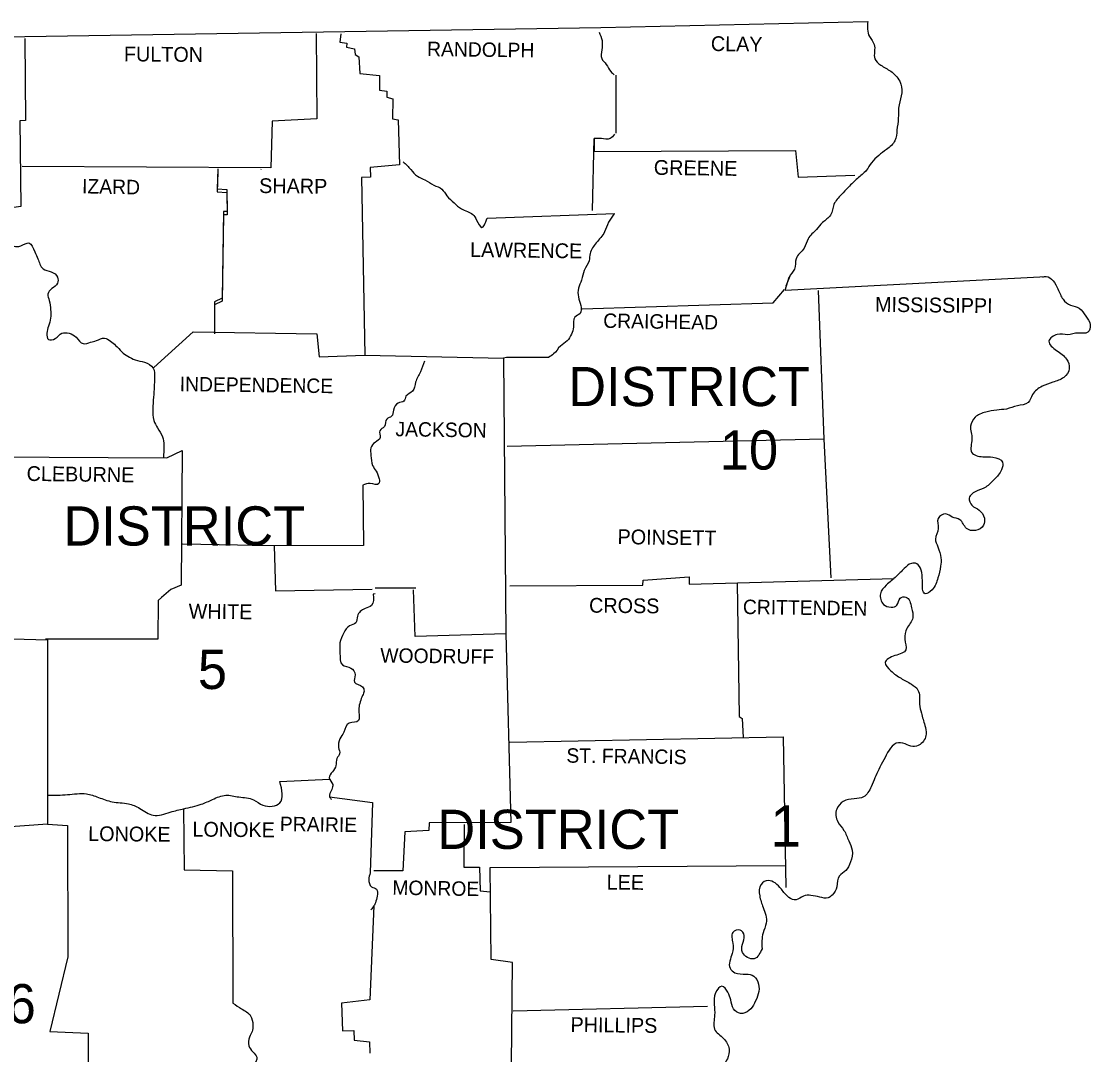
# Model space of a CAD drawing. Extents: x -33639 to 34530, y -17264 to 5867.
# Drawn here: x 2998 to 4708, y 4213 to 5867 of the extents above; entities that cross this region are included whole.
import ezdxf

# ---------------------------------------------------------------- set-up
doc = ezdxf.new("R2010")
doc.units = 0
for name, color, linetype in [('1', 7, 'Continuous'), ('2', 7, 'Continuous'), ('3', 7, 'Continuous')]:
    doc.layers.add(name, color=color, linetype=linetype)

msp = doc.modelspace()

# ---------------------------------------------------------------- linework, layer by layer
at = {"layer": '1'}
for p, q in [((4219.3, 5436.9), (4225.9, 5457.3)), ((4221, 5443.5), (4227.6, 5459.5)), ((3563.3, 4960.3), (3628.8, 4960.3))]:
    msp.add_line(p, q, dxfattribs=at)
for points in [[(1332.2, 5841.4), (2222.1, 5840.9), (3003, 5842.5), (3924.3, 5856.8), (4351.4, 5866.7)], [(3003, 5839.2), (3004.1, 5708.2), (2994.8, 5707.7), (2996.4, 5570.7), (2957.9, 5565.2), (2961.2, 5528.3), (2974.4, 5511.2), (2973.3, 5467.7), (2898.5, 5465), (2895.7, 5397.8), (2827.5, 5395.6), (2824.2, 5314.2), (2828, 5307.6), (2829.7, 5177.7), (2947.5, 5170), (2945.8, 4880), (3039.4, 4877.2), (3039.4, 4582.2), (2965.6, 4576.7), (2960.1, 4511.8), (2836.3, 4511.2)], [(3469.2, 5847.5), (3470.3, 5711), (3398.7, 5707.1), (3396.5, 5632.3), (2998.6, 5634.5)], [(3508.8, 5846.9), (3507.2, 5833.7), (3518.2, 5832.1), (3517.6, 5825.5), (3530.3, 5822.7), (3531.4, 5813.9), (3537.4, 5810.1), (3539.1, 5783.6), (3570.5, 5780.3), (3570.5, 5756.7), (3582, 5755), (3582, 5745.7), (3591.9, 5742.9), (3591.4, 5711), (3600.2, 5709.3), (3602.4, 5637.2), (3555.6, 5632.8), (3556.1, 5617.4), (3541.8, 5616.9), (3546.8, 5332.9), (3768.6, 5327.9), (3772.4, 4886.6), (3627.7, 4882.7), (3624.9, 4957)], [(3948.5, 5780.9), (3948.5, 5687.9)], [(3911.1, 5564.1), (3913.9, 5679.1), (3913.9, 5658.7), (4235.8, 5660.4), (4240.2, 5617.4), (4331, 5620.7)], [(3311.8, 5630.6), (3310.7, 5598.7), (3326.1, 5597.6), (3326.6, 5562.4), (3321.1, 5562.4), (3318.9, 5423.7), (3306.3, 5418.2), (3306.3, 5372)], [(3380.6, 5629.5), (3381.1, 5630.1)], [(3311.8, 5625.7), (3310.7, 5593.8), (3326.1, 5592.7), (3326.6, 5557.4), (3321.1, 5557.4), (3318.9, 5418.8), (3306.3, 5413.3), (3306.3, 5367)], [(3742.7, 5551.9), (3946.9, 5559.1)], [(4219.3, 5436.9), (4637, 5458.4)], [(3894.6, 5406.7), (4200.1, 5416.6), (4218.2, 5437.5)], [(4272.2, 5436.4), (4281.5, 5198.1), (4292.5, 4976.3)], [(3209.4, 5313.1), (3272.2, 5369.8), (3470.3, 5367), (3474.1, 5330.2), (3546.2, 5332.9)], [(3840.7, 5329.1), (3773.5, 5329.1), (3768.6, 5327.9)], [(4281.5, 5198.1), (3774.6, 5186.5)], [(2947.5, 5170), (3230.3, 5168.3), (3254.6, 5179.9), (3252.9, 4964.7), (3236.4, 4957.6), (3221.5, 4944.9), (3216.6, 4940), (3216, 4878.3), (3036.1, 4878.3)], [(3544, 5124.9), (3545.1, 5028), (3402, 5027.5), (3255.1, 5030.2)], [(3402, 5027.5), (3404.2, 4955.4), (3558.9, 4958.1)], [(3779, 4963.6), (3991.5, 4964.7), (3992, 4972.4), (4065.8, 4977.9), (4065.8, 4966.4), (4393.5, 4975.4)], [(4142.8, 4968.5), (4145.6, 4754.5), (4150.5, 4751.2), (4152.3, 4720.7)], [(3563.3, 4951), (3560.5, 4950.4)], [(3772.4, 4886.6), (3780.7, 4585), (3649.7, 4584.4), (3649.2, 4572.3), (3611.2, 4570.1), (3607.9, 4507.4), (3561.6, 4507.4)], [(3779, 4713.2), (4216, 4722)], [(4216, 4722), (4220.4, 4481)], [(3410.9, 4650.5), (3490.7, 4654.3)], [(3490.7, 4625.7), (3559.4, 4616.9), (3555.6, 4504.6)], [(3256.8, 4607.5), (3257.9, 4509), (3335.5, 4507.4), (3336, 4296)], [(3039.4, 4582.2), (3071.3, 4580), (3071.8, 4369.8), (3043.2, 4250.4), (3104.3, 4247.6), (3103.8, 4146.3)], [(3705.8, 4581.7), (3705.3, 4513.4), (3730.6, 4513.4), (3731.7, 4475.5), (3747.7, 4473.8)], [(3770.2, 4024.7), (3822, 4028), (3821.4, 4139.7), (3781.2, 4142.5), (3783.4, 4361), (3748.8, 4365.9), (3747.7, 4512.9), (4219.8, 4516.2)], [(3561.6, 4451.8), (3555, 4301), (3509.9, 4296), (3511, 4251.5), (3529.2, 4252), (3529.7, 4236.6), (3554.5, 4233.8), (3555, 4215.7)], [(3784.5, 4283.4), (4094.9, 4291.1)]]:
    msp.add_lwpolyline(points, dxfattribs=at)
for points in [[(4351.4, 5866.7), (4354.2, 5842.5), (4361.9, 5829.9), (4363, 5806.8), (4372.3, 5796.9), (4388.3, 5786.9), (4402.6, 5771), (4405.9, 5752.3), (4401.5, 5733), (4400.4, 5711.5), (4398.2, 5692.8), (4394.9, 5675.8), (4381.7, 5662), (4369, 5652.1), (4357.5, 5640.6), (4349.2, 5628.4), (4334.9, 5615.2), (4320.6, 5601.5), (4309, 5589.4), (4297.5, 5574), (4292, 5556.9), (4279.3, 5544.8), (4269.4, 5533.8), (4256.2, 5518.9), (4249.6, 5504.1), (4236.9, 5487), (4234.2, 5470.5), (4225.9, 5457.3), (4225.4, 5455.1)], [(3921.6, 5849.7), (3926.5, 5835.9), (3926, 5821.1), (3926, 5807.3), (3933.1, 5798), (3940.3, 5786.4), (3945.8, 5781.4)], [(3946.3, 5686.2), (3939.2, 5679.1), (3925.4, 5679.1), (3913.9, 5679.1)], [(3608.4, 5642.2), (3620.5, 5629.5), (3631, 5619.1), (3643.1, 5613), (3657.4, 5604.8), (3670.1, 5598.2), (3678.3, 5587.7), (3689.9, 5576.2), (3701.4, 5566.8), (3719.6, 5558), (3725.7, 5548.6), (3733.9, 5537.1), (3742.7, 5551.9)], [(3945.2, 5558.5), (3937, 5545.3), (3930.4, 5529.9), (3917.2, 5512.3), (3907.3, 5495.3), (3905.6, 5483.7), (3897.9, 5468.3), (3893.5, 5452.9), (3888.6, 5439.7), (3888.6, 5425.9), (3892.4, 5412.2), (3891.3, 5399.5), (3883.1, 5393.4), (3880.9, 5377.5), (3877.6, 5366.5), (3870.4, 5355.5), (3859.9, 5347.2), (3848.9, 5334.6), (3840.7, 5329.1)], [(2974.4, 5511.2), (2996.4, 5507.4), (3009.6, 5512.3), (3019, 5498), (3024, 5487), (3032.2, 5471), (3045.4, 5466.1), (3055.3, 5457.3), (3055.3, 5447.9), (3046.5, 5439.1), (3039.9, 5430.3), (3042.1, 5419.9), (3044.3, 5405.5), (3044.3, 5391.8), (3041, 5379.1), (3038.3, 5367.6), (3041, 5357.7), (3051.5, 5359.3), (3062.5, 5367.6), (3074, 5367.6), (3085, 5361.5), (3096.6, 5351.1), (3108.2, 5353.3), (3117.5, 5356), (3130.7, 5359.9), (3140.1, 5354.9), (3148.3, 5348.3), (3158.2, 5337.9), (3167.6, 5331.3), (3179.7, 5325.2), (3194.6, 5321.3), (3208.3, 5312), (3210.5, 5296), (3210, 5282.3), (3208.9, 5265.2), (3207.8, 5246.5), (3209.4, 5228.3), (3215.5, 5216.2), (3223.2, 5201.9), (3225.4, 5188.7), (3224.8, 5167.8)], [(4631, 5457.8), (4637, 5458.4), (4655.8, 5438.6), (4664, 5422.1), (4676.1, 5412.7), (4689.9, 5407.8), (4700.3, 5395.1), (4707.5, 5381.3), (4703.6, 5369.2), (4688.2, 5368.1), (4671.2, 5365.4), (4654.7, 5365.9), (4641.4, 5354.9), (4653.5, 5340.1), (4669.5, 5326.3), (4673.9, 5311.4), (4665.1, 5297.1), (4647.5, 5289.4), (4630.4, 5282.8), (4615, 5269.6), (4607.9, 5257), (4590.8, 5251.5), (4573.2, 5246.5), (4557.8, 5244.8), (4540.2, 5241.5), (4523.1, 5233.3), (4516, 5219), (4518.2, 5198.6), (4517.6, 5177.2), (4535.8, 5170), (4551.7, 5169.4), (4567.1, 5161.2), (4565.5, 5149.1), (4553.9, 5133.7), (4540.2, 5121.6), (4526.4, 5115.5), (4513.8, 5104), (4518.2, 5092.4), (4529.7, 5084.7), (4538, 5072), (4536.9, 5060.5), (4523.7, 5052.2), (4509.4, 5055.5), (4498.9, 5069.3), (4486.8, 5073.7), (4476.3, 5078.6), (4464.2, 5071.5), (4464.2, 5055.5), (4459.8, 5038.5), (4463.7, 5025.8), (4468.6, 5008.2), (4468.1, 4995), (4463.7, 4976.3), (4454.3, 4957), (4443.3, 4951), (4438.9, 4971.9), (4436.7, 4988.9), (4430.1, 4998.8), (4421.3, 4999.4), (4409.7, 4991.1), (4397.1, 4978.5), (4381.1, 4964.7), (4371.8, 4951), (4376.7, 4933.9), (4388.8, 4929.5), (4398.2, 4932.8), (4403.1, 4943.8), (4412.5, 4945.5), (4421.3, 4928.4)], [(3642.5, 5323), (3635.9, 5305.9), (3628.2, 5289.4), (3623.3, 5275.1), (3612.8, 5266.9), (3609.5, 5259.2), (3600.2, 5255.9), (3593, 5244.8), (3589.7, 5234.9), (3582, 5230.5), (3578.2, 5218.4), (3571, 5211.8), (3571.6, 5200.8), (3563.3, 5193.1), (3556.7, 5184.3), (3556.7, 5172.2), (3559.4, 5156.2), (3564.9, 5146.9), (3569.9, 5134.8), (3569.4, 5127.1), (3555.6, 5127.1), (3544, 5124.9)], [(3560.5, 4950.4), (3557.8, 4932.2), (3547.3, 4927.3), (3535.2, 4915.2), (3532.5, 4904.2), (3522.6, 4899.8), (3513.2, 4888.2), (3507.2, 4872.3), (3507.2, 4855.7), (3511, 4837), (3524.8, 4832.1), (3531.4, 4821.1), (3530.3, 4809.5), (3543.5, 4801.8), (3545.7, 4795.2), (3543.5, 4788.1), (3537.4, 4767.7), (3538, 4753.9), (3536.9, 4747.9), (3522, 4744), (3513.2, 4729.2), (3507.2, 4718.7), (3505, 4704.9), (3506.6, 4695), (3502.2, 4687.3), (3500.6, 4675.8), (3495.1, 4665.9), (3490.1, 4656.5), (3495.6, 4645.5), (3494, 4637.8), (3490.7, 4625.7), (3493.4, 4621.8)], [(4421.3, 4928.4), (4423.5, 4912.4), (4414.1, 4895.4), (4410.8, 4878.3), (4412.5, 4861.2), (4394.9, 4851.9), (4379.5, 4840.9), (4388.3, 4827.7), (4404.8, 4815.6), (4421.3, 4806.2), (4431.8, 4796.9), (4434.5, 4774.3), (4437.3, 4760), (4442.8, 4740.2), (4445, 4726.4), (4435.1, 4709.9), (4423.5, 4706.6), (4411.4, 4710.5), (4397.1, 4711.6), (4385.5, 4700.5), (4377.3, 4685.1), (4369, 4669.7), (4363, 4656.5), (4356.9, 4642.2), (4344.8, 4625.7), (4329.9, 4622.9), (4312.3, 4618.5), (4301.9, 4606.4), (4303.5, 4586.1), (4313.4, 4572.3), (4321.1, 4555.3), (4326.6, 4540.4), (4323.9, 4521.7), (4316.2, 4507.9), (4306.3, 4499.7), (4301.9, 4482.1), (4294.7, 4468.8), (4288.1, 4464.4), (4274.9, 4465.5), (4260.6, 4468.3), (4248.5, 4467.2), (4236.9, 4461.1), (4225.4, 4465), (4213.3, 4478.2), (4203.4, 4488.1), (4192.4, 4492), (4180.8, 4485.9), (4178.6, 4467.7), (4184.1, 4449), (4189.1, 4423.7), (4184.1, 4408.3), (4182.4, 4383)], [(3040.5, 4628.5), (3071.3, 4629.6), (3101.6, 4630.7), (3120.8, 4625.1), (3142.8, 4618), (3168.7, 4614.7), (3186.9, 4607.5), (3208.3, 4596.5), (3235.8, 4601.5), (3257.3, 4607), (3285.4, 4614.1), (3303.5, 4621.8), (3324.4, 4628.5), (3345.4, 4625.7), (3369, 4621.3), (3383.9, 4612.5), (3410.9, 4616.3), (3410.9, 4650.5)], [(3555.6, 4504.6), (3553.4, 4493.6), (3557.8, 4482.1), (3565.5, 4478.2), (3566.6, 4467.2), (3563.8, 4456.2), (3561.6, 4451.8), (3556.7, 4445.2)], [(4182.4, 4383), (4169.8, 4367), (4151.1, 4376.9), (4151.1, 4390.1), (4153.8, 4403.9), (4147.2, 4412.7), (4135.7, 4408.9), (4135.7, 4391.8), (4134.6, 4375.3), (4131.3, 4351.6), (4139, 4344.5), (4156.6, 4342.3), (4169.2, 4339), (4176.9, 4326.3), (4176.4, 4310.9), (4170.3, 4296), (4161.5, 4283.9), (4147.8, 4279.5), (4136.8, 4286.7), (4132.4, 4301), (4127.4, 4313.6), (4118.1, 4323), (4108.1, 4312.5), (4105.9, 4293.3), (4106.5, 4276.8), (4106.5, 4254.2), (4120.8, 4239.3), (4129.6, 4222.3), (4126.9, 4206.9), (4116.4, 4188.7), (4112, 4172.8), (4107.6, 4151.3), (4108.1, 4127.6), (4104.3, 4104.5), (4096.6, 4089.1), (4082.3, 4076.4), (4072.9, 4068.2), (4065.2, 4059.9), (4061.4, 4043.4), (4058.6, 4031.9), (4048.2, 4018.1), (4039.9, 4017), (4033.3, 4022.5), (4031.1, 4031.9), (4031.1, 4041.2), (4026.7, 4050.6), (4012.9, 4054.4), (4001.9, 4053.9), (3997, 4046.2), (4004.1, 4024.7), (4006.9, 4011), (4003, 3992.2), (4005.2, 3990), (3985.4, 3979.6), (3969.5, 3977.9), (3956.3, 3974.1), (3943.6, 3965.8), (3937.5, 3953.7), (3928.7, 3943.8), (3921, 3934.5), (3910.6, 3930.1), (3899, 3932.3), (3883.6, 3933.9), (3874.8, 3922.9), (3877.6, 3906.9), (3888, 3897.6), (3903.4, 3893.2), (3919.4, 3894.3), (3934.8, 3895.9), (3949.1, 3888.2), (3946.3, 3873.4), (3932.6, 3866.2), (3912.2, 3864), (3895.7, 3865.7), (3875.9, 3861.3), (3866, 3848.6), (3871.5, 3829.3), (3893, 3821.6), (3902.9, 3803.5), (3903.4, 3786.4), (3896.3, 3763.8), (3886.4, 3753.4), (3867.1, 3749), (3852.2, 3746.2), (3850, 3720.9), (3843.4, 3708.3), (3831.9, 3704.4), (3815.4, 3712.7), (3805.5, 3716.5), (3793.3, 3722), (3777.9, 3731.4), (3766.4, 3729.7), (3769.7, 3705.5), (3770.8, 3704.4), (3784, 3686.2), (3797.2, 3671.9), (3803.3, 3654.9)], [(3336, 4296), (3349.8, 4286.7), (3364.1, 4275.7), (3367.9, 4260.8), (3366.8, 4250.4), (3362.4, 4241.6), (3361.3, 4227.8), (3367.9, 4217.9), (3374, 4209.6), (3367.9, 4194.8), (3357.5, 4181), (3352, 4165.6), (3348.1, 4142.5)]]:
    msp.add_spline(points, degree=3, dxfattribs=at)

# ---------------------------------------------------------------- texts
msp.add_text('1', height=66, dxfattribs=at).set_placement((4195.7, 4546.4))
at = {"layer": '2'}
for s, height, rotation, p in [('RANDOLPH', 23.11, 359.2583, (3646.4, 5811.2)), ('CLAY', 23.66, 359.2258, (4100.4, 5819.4)), ('FULTON', 23.66, 359.4996, (3161.5, 5802.9)), ('GREENE', 23.67, 359.2361, (4009.1, 5621.3)), ('IZARD', 23.11, 358.9258, (3094.4, 5591.6)), ('SHARP', 23.66, 359.3905, (3377.8, 5592.1)), ('LAWRENCE', 23.67, 359.2678, (3715.2, 5489.8)), ('MISSISSIPPI', 23.66, 359.3097, (4363, 5402.2)), ('CRAIGHEAD', 23.11, 359.1159, (3928.2, 5376.4)), ('INDEPENDENCE', 23.108, 359.2187, (3250.7, 5275.1)), ('JACKSON', 23.11, 359.1352, (3595.8, 5203)), ('CLEBURNE', 23.66, 359.2535, (3005.8, 5131.5)), ('POINSETT', 23.66, 359.1987, (3951.1, 5030.4)), ('CROSS', 23.66, 359.3839, (3905.6, 4920.7)), ('WHITE', 23.67, 359.3139, (3265, 4911.3)), ('CRITTENDEN', 23.11, 359.213, (4151.6, 4918.5)), ('WOODRUFF', 23.11, 359.2748, (3571.6, 4840.9)), ('ST. FRANCIS', 23.108, 359.2216, (3869.3, 4680.7)), ('LONOKE', 23.67, 359.4974, (3271.1, 4562.4)), ('PRAIRIE', 23.11, 359.2116, (3410.9, 4571.2)), ('LONOKE', 23.67, 359.4974, (3104.3, 4555.3)), ('LEE', 23.67, 359.4327, (3933.7, 4477.7)), ('MONROE', 23.11, 359.0331, (3590.8, 4469.4)), ('PHILLIPS', 23.66, 359.3179, (3875.9, 4249.8))]:
    msp.add_text(s, height=height, rotation=rotation, dxfattribs=at).set_placement(p)
at = {"layer": '3'}
for s, height, p in [('DISTRICT', 62.74, (3872.3, 5251.1)), ('10', 62.74, (4114.8, 5149.6)), ('DISTRICT', 62.74, (3064.7, 5028)), ('5', 62.7, (3279.9, 4798.5)), ('DISTRICT', 62.74, (3662.9, 4542.6)), ('DISTRICT 6', 62.74, (2563.9, 4263.6))]:
    msp.add_text(s, height=height, dxfattribs=at).set_placement(p)

doc.saveas('drawing.dxf')
